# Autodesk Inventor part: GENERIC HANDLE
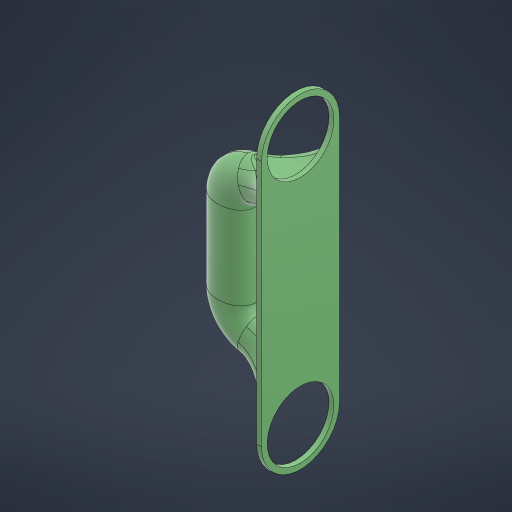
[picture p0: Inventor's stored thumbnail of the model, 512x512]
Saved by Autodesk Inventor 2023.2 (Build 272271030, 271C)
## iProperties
Created: 2023-04
Part Number: GENERIC HANDLE
Material: Generic
Document SubType Name: Modeling
Designer: AR
Mass: 182.286 g
Surface Area: 432.452 cm^2
Volume: 182.286 cm^3
Density: 1 g/cm^3
Appearance: Default
Author: AR
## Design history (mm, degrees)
derived "_2 SPOOL CORD WRAP MP.ipt"
tag "TaggingFeature1"
feature "GENERIC HANDLE COMBINED::_2 SPOOL CORD WRAP MP.ipt" dims "d0" = 10
node "GENERIC HANDLE"
node "GENERIC HANDLE COMBINED"
